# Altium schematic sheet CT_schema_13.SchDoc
size 390 x 385 mm
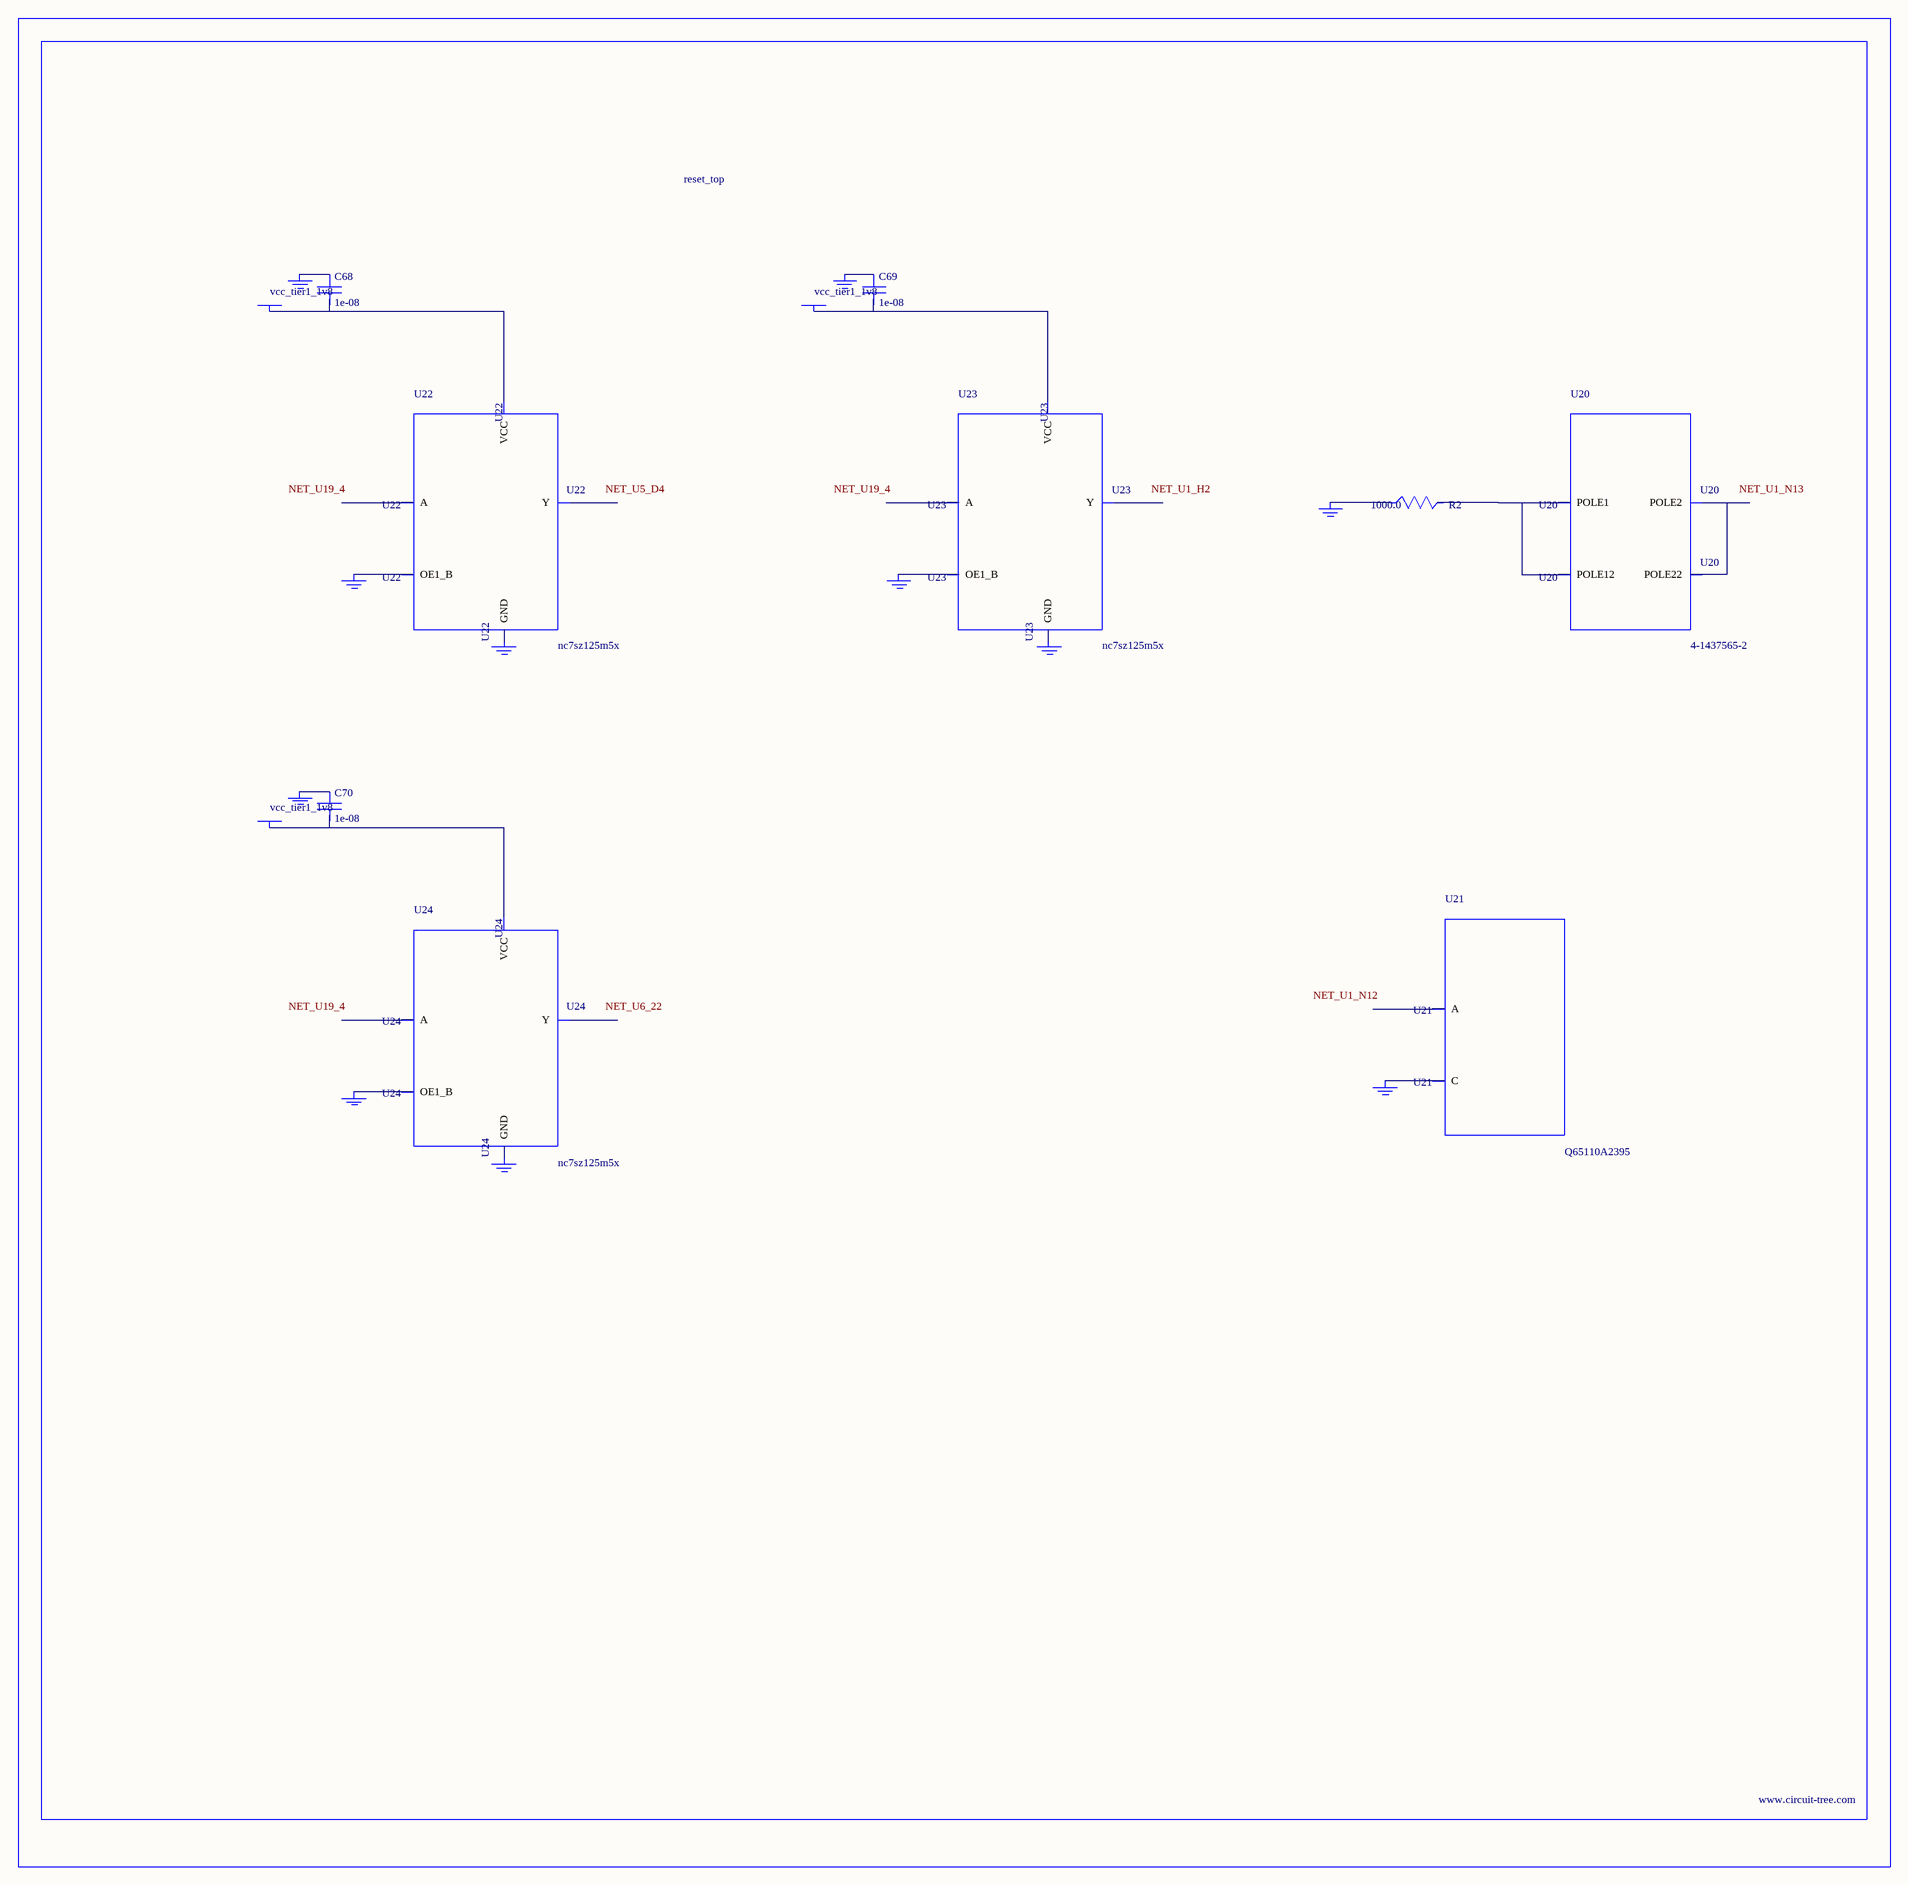
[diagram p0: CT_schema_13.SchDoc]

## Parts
BORDER12  (no value)
C68  1e-08  [C0402]
C69  1e-08  [C0402]
C70  1e-08  [C0402]
GND_INSTANCE_12_0  (no value)
GND_INSTANCE_12_1  (no value)
GND_INSTANCE_12_2  (no value)
GND_INSTANCE_12_3  (no value)
GND_INSTANCE_12_4  (no value)
GND_INSTANCE_12_5  (no value)
GND_INSTANCE_12_6  (no value)
GND_INSTANCE_12_7  (no value)
GND_INSTANCE_12_8  (no value)
GND_INSTANCE_12_9  (no value)
GND_INSTANCE_12_10  (no value)
POWER_INSTANCE_12_0  vcc_tier1_1v8
POWER_INSTANCE_12_1  vcc_tier1_1v8
POWER_INSTANCE_12_2  vcc_tier1_1v8
R2  1000.0  [R0603]
U20  4-1437565-2  [SW_4-1437565-2]
U21  Q65110A2395  [LGM67K-G1J2-24-Z]
U22  nc7sz125m5x  [NC7SZ125M5X]
U23  nc7sz125m5x  [NC7SZ125M5X]
U24  nc7sz125m5x  [NC7SZ125M5X]

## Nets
NetC68_1: C68.1 GND_INSTANCE_12_2.0(GND)
NetC68_2: C68.2 POWER_INSTANCE_12_0.0(PWR) U22.5(VCC)
NetC69_1: C69.1 GND_INSTANCE_12_5.0(GND)
NetC69_2: C69.2 POWER_INSTANCE_12_1.0(PWR) U23.5(VCC)
NetC70_1: C70.1 GND_INSTANCE_12_8.0(GND)
NetC70_2: C70.2 POWER_INSTANCE_12_2.0(PWR) U24.5(VCC)
NetGND_INSTANCE_12_0_0: GND_INSTANCE_12_0.0(GND) R2.1
NetGND_INSTANCE_12_1_0: GND_INSTANCE_12_1.0(GND) U21.C
NetGND_INSTANCE_12_3_0: GND_INSTANCE_12_3.0(GND) U22.1(OE1_B)
NetGND_INSTANCE_12_4_0: GND_INSTANCE_12_4.0(GND) U22.3(GND)
NetGND_INSTANCE_12_6_0: GND_INSTANCE_12_6.0(GND) U23.1(OE1_B)
NetGND_INSTANCE_12_7_0: GND_INSTANCE_12_7.0(GND) U23.3(GND)
NetGND_INSTANCE_12_9_0: GND_INSTANCE_12_9.0(GND) U24.1(OE1_B)
NetGND_INSTANCE_12_10_0: GND_INSTANCE_12_10.0(GND) U24.3(GND)
NetR2_2: R2.2 U20.1(POLE1) U20.2(POLE12)
NetU20_3: U20.3(POLE2) U20.4(POLE22)

Not connected (* = marked no-connect by the designer): U21 A; U22 2(A) 4(Y); U23 2(A) 4(Y); U24 2(A) 4(Y)

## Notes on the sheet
- Labels drawn without touching a wire or pin: NET_U1_H2, NET_U1_N12, NET_U1_N13, NET_U5_D4, NET_U6_22, NET_U19_4

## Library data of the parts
BORDER12 = BORDER_PAGE12
C68-C70 = C0402C103K3RAC
GND_INSTANCE_12_0-GND_INSTANCE_12_10 = GND
POWER_INSTANCE_12_0-POWER_INSTANCE_12_2 = PWR
R2 = RC0603JR-071KL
